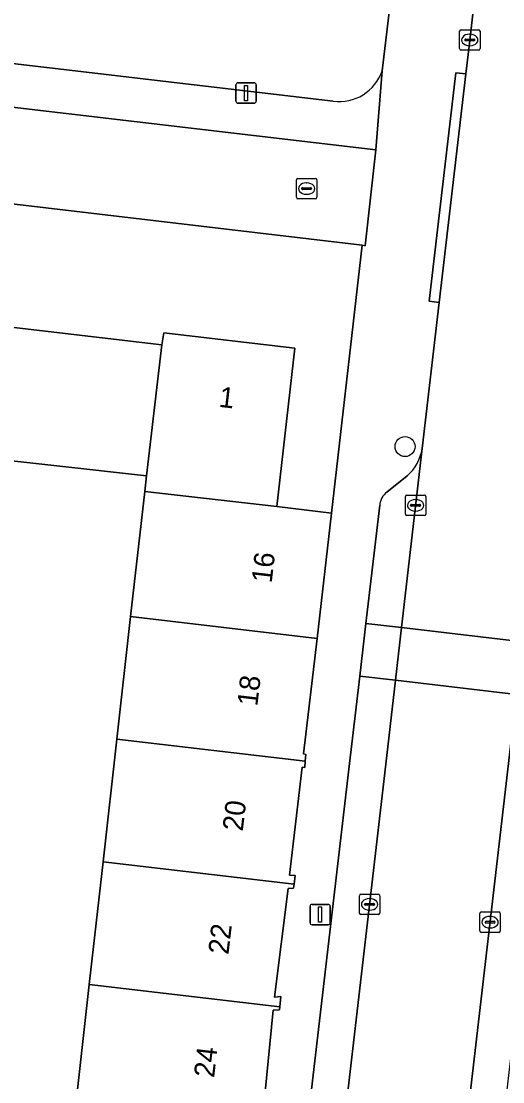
# Model space of a CAD drawing. Extents: x 161241 to 161758, y 384138 to 384885.
# Drawn here: x 161433.6 to 161457.1, y 384527.4 to 384579.4 of the extents above; entities that cross this region are included whole.
import ezdxf

# ---------------------------------------------------------------- set-up
doc = ezdxf.new("R2010")
doc.units = 0
for name, color, linetype in [('IMGEO_Boom', 7, 'Continuous'), ('IMGEO_Erf', 7, 'Continuous'), ('IMGEO_Kolk', 7, 'Continuous'), ('IMGEO_Lichtmast', 7, 'Continuous'), ('IMGEO_Pand', 7, 'Continuous'), ('IMGEO_Pand_nummerreeks', 7, 'Continuous'), ('IMGEO_Parkeervlak_open', 7, 'Continuous'), ('IMGEO_Rijbaan_lokaal_open', 7, 'Continuous'), ('IMGEO_Voetpad_open', 7, 'Continuous')]:
    doc.layers.add(name, color=color, linetype=linetype)

msp = doc.modelspace()

# ---------------------------------------------------------------- linework, layer by layer
at = {"layer": 'IMGEO_Boom'}
msp.add_circle((161452.348, 384558.545), 0.489, dxfattribs=at)
at = {"layer": 'IMGEO_Erf'}
for points in [[(161451.231, 384576.957), (161452.444, 384587.078)], [(161393.526, 384581.977), (161448.824, 384575.465)], [(161431.664, 384564.552), (161440.436, 384563.525), (161440.534, 384564.111), (161446.954, 384563.36), (161446.076, 384555.602), (161448.755, 384555.29), (161450.255, 384568.412), (161432.118, 384570.547)], [(161436.213, 384526.177), (161436.887, 384532.189), (161437.562, 384538.199), (161438.237, 384544.211), (161438.911, 384550.221), (161439.599, 384556.349), (161439.684, 384557.106), (161430.889, 384558.093)]]:
    msp.add_lwpolyline(points, dxfattribs=at)
msp.add_arc((161449.133, 384577.654), 2.21, 261.9554, 341.6307, dxfattribs=at)
at = {"layer": 'IMGEO_Kolk'}
for p, q in [((161455.094, 384578.962), (161455.946, 384578.962)), ((161455.019, 384578.036), (161455.019, 384578.888)), ((161455.278, 384578.456), (161455.278, 384578.468)), ((161455.716, 384578.419), (161455.318, 384578.419)), ((161455.321, 384578.505), (161455.719, 384578.505)), ((161455.507, 384578.742), (161455.532, 384578.742)), ((161455.762, 384578.468), (161455.762, 384578.456)), ((161456.02, 384578.888), (161456.02, 384578.036)), ((161455.946, 384577.962), (161455.094, 384577.962)), ((161455.53, 384578.182), (161455.505, 384578.182)), ((161447.103, 384571.68), (161447.955, 384571.68)), ((161447.028, 384570.754), (161447.028, 384571.606)), ((161447.287, 384571.174), (161447.287, 384571.186)), ((161447.725, 384571.137), (161447.327, 384571.137)), ((161447.33, 384571.223), (161447.728, 384571.223)), ((161447.516, 384571.46), (161447.541, 384571.46)), ((161447.771, 384571.186), (161447.771, 384571.174)), ((161448.029, 384571.606), (161448.029, 384570.754)), ((161447.955, 384570.68), (161447.103, 384570.68)), ((161447.539, 384570.9), (161447.514, 384570.9)), ((161452.365, 384555.24), (161452.365, 384556.092)), ((161452.44, 384556.166), (161453.292, 384556.166)), ((161453.366, 384556.092), (161453.366, 384555.24)), ((161452.624, 384555.66), (161452.624, 384555.672)), ((161453.062, 384555.623), (161452.664, 384555.623)), ((161452.667, 384555.709), (161453.065, 384555.709)), ((161452.853, 384555.946), (161452.878, 384555.946)), ((161453.108, 384555.672), (161453.108, 384555.66)), ((161453.292, 384555.166), (161452.44, 384555.166)), ((161452.876, 384555.386), (161452.851, 384555.386)), ((161450.111, 384535.694), (161450.111, 384536.546)), ((161450.186, 384536.62), (161451.038, 384536.62)), ((161450.599, 384536.4), (161450.624, 384536.4)), ((161451.112, 384536.546), (161451.112, 384535.694)), ((161450.37, 384536.114), (161450.37, 384536.126)), ((161450.808, 384536.077), (161450.41, 384536.077)), ((161450.413, 384536.163), (161450.811, 384536.163)), ((161450.622, 384535.84), (161450.597, 384535.84)), ((161450.854, 384536.126), (161450.854, 384536.114)), ((161451.038, 384535.62), (161450.186, 384535.62)), ((161456.013, 384534.822), (161456.013, 384535.674)), ((161456.088, 384535.748), (161456.94, 384535.748)), ((161456.315, 384535.291), (161456.713, 384535.291)), ((161456.501, 384535.528), (161456.526, 384535.528)), ((161457.014, 384535.674), (161457.014, 384534.822)), ((161456.94, 384534.748), (161456.088, 384534.748)), ((161456.272, 384535.242), (161456.272, 384535.254)), ((161456.71, 384535.205), (161456.312, 384535.205)), ((161456.524, 384534.968), (161456.499, 384534.968)), ((161456.756, 384535.254), (161456.756, 384535.242))]:
    msp.add_line(p, q, dxfattribs=at)
for points in [[(161455.094, 384578.962), (161455.946, 384578.962)], [(161455.019, 384578.036), (161455.019, 384578.888)], [(161456.02, 384578.888), (161456.02, 384578.036)], [(161455.946, 384577.962), (161455.094, 384577.962)], [(161447.103, 384571.68), (161447.955, 384571.68)], [(161447.028, 384570.754), (161447.028, 384571.606)], [(161448.029, 384571.606), (161448.029, 384570.754)], [(161447.955, 384570.68), (161447.103, 384570.68)], [(161452.365, 384555.24), (161452.365, 384556.092)], [(161452.44, 384556.166), (161453.292, 384556.166)], [(161453.366, 384556.092), (161453.366, 384555.24)], [(161453.292, 384555.166), (161452.44, 384555.166)], [(161450.111, 384535.694), (161450.111, 384536.546)], [(161450.186, 384536.62), (161451.038, 384536.62)], [(161451.112, 384536.546), (161451.112, 384535.694)], [(161451.038, 384535.62), (161450.186, 384535.62)], [(161456.013, 384534.822), (161456.013, 384535.674)], [(161456.088, 384535.748), (161456.94, 384535.748)], [(161457.014, 384535.674), (161457.014, 384534.822)], [(161456.94, 384534.748), (161456.088, 384534.748)]]:
    msp.add_lwpolyline(points, dxfattribs=at)
for centre, radius, start, end in [((161455.096, 384578.886), 0.0765, 91.552, 178.448), ((161455.096, 384578.886), 0.0765, 91.552, 178.448), ((161455.944, 384578.886), 0.0765, 1.552, 88.448), ((161455.944, 384578.886), 0.0765, 1.552, 88.448), ((161455.318, 384578.465), 0.0403, 85.8775, 175.7526), ((161455.315, 384578.455), 0.0366, 178.938, 274.7102), ((161455.719, 384578.462), 0.043, 264.8664, 352.4533), ((161455.723, 384578.467), 0.0386, 1.7309, 96.639), ((161455.096, 384578.038), 0.0765, 181.552, 268.448), ((161455.096, 384578.038), 0.0765, 181.552, 268.448), ((161455.944, 384578.038), 0.0765, 271.552, 358.448), ((161455.944, 384578.038), 0.0765, 271.552, 358.448), ((161447.105, 384571.604), 0.0765, 91.552, 178.448), ((161447.105, 384571.604), 0.0765, 91.552, 178.448), ((161447.953, 384571.604), 0.0765, 1.552, 88.448), ((161447.953, 384571.604), 0.0765, 1.552, 88.448), ((161447.327, 384571.183), 0.0403, 85.8775, 175.7526), ((161447.324, 384571.173), 0.0366, 178.938, 274.7102), ((161447.728, 384571.18), 0.043, 264.8664, 352.4533), ((161447.732, 384571.185), 0.0386, 1.7309, 96.639), ((161447.105, 384570.756), 0.0765, 181.552, 268.448), ((161447.105, 384570.756), 0.0765, 181.552, 268.448), ((161447.953, 384570.756), 0.0765, 271.552, 358.448), ((161447.953, 384570.756), 0.0765, 271.552, 358.448), ((161452.442, 384556.09), 0.0765, 91.552, 178.448), ((161452.442, 384556.09), 0.0765, 91.552, 178.448), ((161453.29, 384556.09), 0.0765, 1.552, 88.448), ((161453.29, 384556.09), 0.0765, 1.552, 88.448), ((161452.664, 384555.669), 0.0403, 85.8775, 175.7526), ((161452.661, 384555.659), 0.0366, 178.938, 274.7102), ((161453.065, 384555.666), 0.043, 264.8664, 352.4533), ((161453.069, 384555.671), 0.0386, 1.7309, 96.639), ((161452.442, 384555.242), 0.0765, 181.552, 268.448), ((161452.442, 384555.242), 0.0765, 181.552, 268.448), ((161453.29, 384555.242), 0.0765, 271.552, 358.448), ((161453.29, 384555.242), 0.0765, 271.552, 358.448), ((161450.188, 384536.544), 0.0765, 91.552, 178.448), ((161450.188, 384536.544), 0.0765, 91.552, 178.448), ((161451.036, 384536.544), 0.0765, 1.552, 88.448), ((161451.036, 384536.544), 0.0765, 1.552, 88.448), ((161450.41, 384536.123), 0.0403, 85.8775, 175.7526), ((161450.407, 384536.113), 0.0366, 178.938, 274.7102), ((161450.811, 384536.12), 0.043, 264.8664, 352.4533), ((161450.815, 384536.125), 0.0386, 1.7309, 96.639), ((161450.188, 384535.696), 0.0765, 181.552, 268.448), ((161450.188, 384535.696), 0.0765, 181.552, 268.448), ((161451.036, 384535.696), 0.0765, 271.552, 358.448), ((161451.036, 384535.696), 0.0765, 271.552, 358.448), ((161456.09, 384535.672), 0.0765, 91.552, 178.448), ((161456.09, 384535.672), 0.0765, 91.552, 178.448), ((161456.312, 384535.251), 0.0403, 85.8775, 175.7526), ((161456.717, 384535.253), 0.0386, 1.7309, 96.639), ((161456.938, 384535.672), 0.0765, 1.552, 88.448), ((161456.938, 384535.672), 0.0765, 1.552, 88.448), ((161456.09, 384534.824), 0.0765, 181.552, 268.448), ((161456.09, 384534.824), 0.0765, 181.552, 268.448), ((161456.309, 384535.241), 0.0366, 178.938, 274.7102), ((161456.713, 384535.248), 0.043, 264.8664, 352.4533), ((161456.938, 384534.824), 0.0765, 271.552, 358.448), ((161456.938, 384534.824), 0.0765, 271.552, 358.448)]:
    msp.add_arc(centre, radius, start, end, dxfattribs=at)
for centre, major_axis, ratio, start_param, end_param in [((161455.506, 384578.462), (-0.387, 0.002), 0.722429, 4.712389, 7.853982), ((161455.531, 384578.462), (-0.39, 0.002), 0.717154, 1.570796, 4.712389), ((161447.515, 384571.18), (-0.387, 0.002), 0.722429, 4.712389, 7.853982), ((161447.54, 384571.18), (-0.39, 0.002), 0.717154, 1.570796, 4.712389), ((161452.852, 384555.666), (-0.387, 0.002), 0.722429, 4.712389, 7.853982), ((161452.877, 384555.666), (-0.39, 0.002), 0.717154, 1.570796, 4.712389), ((161450.598, 384536.12), (-0.387, 0.002), 0.722429, 4.712389, 7.853982), ((161450.623, 384536.12), (-0.39, 0.002), 0.717154, 1.570796, 4.712389), ((161456.5, 384535.248), (-0.387, 0.002), 0.722429, 4.712389, 7.853982), ((161456.525, 384535.248), (-0.39, 0.002), 0.717154, 1.570796, 4.712389)]:
    msp.add_ellipse(centre, major_axis=major_axis, ratio=ratio, start_param=start_param, end_param=end_param, dxfattribs=at)
at = {"layer": 'IMGEO_Lichtmast'}
for p, q in [((161444.169, 384576.363), (161444.959, 384576.363)), ((161444.959, 384576.363), (161444.169, 384576.363)), ((161444.069, 384575.463), (161444.069, 384576.263)), ((161444.069, 384576.263), (161444.069, 384575.463)), ((161445.059, 384576.263), (161445.059, 384575.463)), ((161445.059, 384575.463), (161445.059, 384576.263)), ((161444.959, 384575.363), (161444.169, 384575.363)), ((161444.169, 384575.363), (161444.959, 384575.363)), ((161447.696, 384535.219), (161447.696, 384536.019)), ((161447.696, 384536.019), (161447.696, 384535.219)), ((161447.796, 384536.119), (161448.586, 384536.119)), ((161448.586, 384536.119), (161447.796, 384536.119)), ((161448.686, 384536.019), (161448.686, 384535.219)), ((161448.686, 384535.219), (161448.686, 384536.019)), ((161448.586, 384535.119), (161447.796, 384535.119)), ((161447.796, 384535.119), (161448.586, 384535.119))]:
    msp.add_line(p, q, dxfattribs=at)
for points in [[(161444.489, 384576.238), (161444.639, 384576.238), (161444.639, 384575.488), (161444.489, 384575.488), (161444.489, 384576.238)], [(161448.116, 384535.994), (161448.266, 384535.994), (161448.266, 384535.244), (161448.116, 384535.244), (161448.116, 384535.994)]]:
    msp.add_lwpolyline(points, dxfattribs=at)
for centre, start, end in [((161444.169, 384576.263), 90, 180), ((161444.169, 384576.263), 90, 180), ((161444.959, 384576.263), 0, 90), ((161444.959, 384576.263), 360, 90), ((161444.169, 384575.463), 180, 270), ((161444.169, 384575.463), 180, 270), ((161444.959, 384575.463), 270, 0), ((161444.959, 384575.463), 270, 0), ((161447.796, 384536.019), 90, 180), ((161447.796, 384536.019), 90, 180), ((161448.586, 384536.019), 0, 90), ((161448.586, 384536.019), 360, 90), ((161447.796, 384535.219), 180, 270), ((161447.796, 384535.219), 180, 270), ((161448.586, 384535.219), 270, 0), ((161448.586, 384535.219), 270, 0)]:
    msp.add_arc(centre, 0.1, start, end, dxfattribs=at)
at = {"layer": 'IMGEO_Pand'}
for points in [[(161424.542, 384557.899), (161430.788, 384557.198), (161430.889, 384558.093), (161439.684, 384557.106), (161440.436, 384563.525), (161431.664, 384564.552), (161431.905, 384566.233), (161426.007, 384566.969), (161426.028, 384567.075), (161425.621, 384567.124)], [(161439.684, 384557.106), (161439.599, 384556.349), (161446.076, 384555.602), (161446.954, 384563.36), (161440.534, 384564.111), (161440.436, 384563.525)], [(161448.755, 384555.29), (161446.076, 384555.602), (161439.599, 384556.349), (161438.911, 384550.221), (161448.04, 384549.151)], [(161447.484, 384543.465), (161447.381, 384543.492), (161448.04, 384549.151), (161438.911, 384550.221), (161438.237, 384544.211), (161447.459, 384543.13)], [(161446.969, 384537.535), (161446.688, 384537.543), (161447.308, 384542.844), (161447.437, 384542.828), (161447.459, 384543.13), (161438.237, 384544.211), (161437.562, 384538.199), (161446.916, 384537.102)], [(161446.261, 384531.602), (161445.956, 384531.575), (161446.624, 384536.898), (161446.892, 384536.909), (161446.916, 384537.102), (161437.562, 384538.199), (161436.887, 384532.189), (161446.21, 384531.096)], [(161445.896, 384530.942), (161446.196, 384530.954), (161446.21, 384531.096), (161436.887, 384532.189), (161436.213, 384526.177), (161445.323, 384525.109)]]:
    msp.add_lwpolyline(points, close=True, dxfattribs=at)
at = {"layer": 'IMGEO_Parkeervlak_open'}
for points in [[(161451.107, 384555.678), (161450.43, 384549.88), (161452.178, 384549.677), (161453.187, 384558.455)], [(161452.45, 384557.117), (161451.46, 384556.317)], [(161447.539, 384509.648), (161451.359, 384542.556), (161451.881, 384547.095), (161450.128, 384547.299), (161449.597, 384542.748), (161446.111, 384512.773)], [(161455.567, 384511.666), (161459.568, 384546.2), (161457.814, 384546.404), (161453.447, 384508.842)]]:
    msp.add_lwpolyline(points, dxfattribs=at)
msp.add_lwpolyline([(161450.128, 384547.299), (161451.881, 384547.095), (161452.178, 384549.677), (161450.43, 384549.88)], close=True, dxfattribs=at)
for centre, radius, start, end in [((161451.05, 384558.76), 2.159, 310.4335, 351.8726), ((161452.069, 384555.564), 0.969, 128.9499, 173.2154)]:
    msp.add_arc(centre, radius, start, end, dxfattribs=at)
at = {"layer": 'IMGEO_Rijbaan_lokaal_open'}
for points in [[(161458.88, 384607.496), (161456.155, 384584.108), (161455.501, 384578.293), (161455.326, 384576.798), (161454.02, 384565.608), (161453.187, 384558.455), (161452.178, 384549.677), (161458.115, 384548.986), (161459.149, 384557.883), (161459.972, 384564.87), (161461.287, 384576.027), (161461.494, 384577.785), (161462.171, 384583.365), (161464.9, 384606.794)], [(161452.178, 384549.677), (161451.881, 384547.095), (161457.814, 384546.404), (161458.115, 384548.986)]]:
    msp.add_lwpolyline(points, close=True, dxfattribs=at)
for points in [[(161358.492, 384579.061), (161360.348, 384578.831), (161378.37, 384576.849), (161415.137, 384572.53), (161414.97, 384570.779), (161418.982, 384570.31), (161419.169, 384572.05), (161432.118, 384570.547), (161450.255, 384568.412), (161450.399, 384568.382), (161450.927, 384573.072), (161397.745, 384579.321)], [(161452.684, 384502.539), (161453.058, 384505.828), (161453.447, 384508.842), (161457.814, 384546.404), (161451.881, 384547.095), (161451.359, 384542.556), (161447.539, 384509.648), (161446.771, 384503.468)]]:
    msp.add_lwpolyline(points, dxfattribs=at)
at = {"layer": 'IMGEO_Voetpad_open'}
for points in [[(161452.444, 384587.078), (161451.231, 384576.957), (161450.927, 384573.072), (161450.399, 384568.382), (161450.255, 384568.412), (161448.755, 384555.29), (161448.04, 384549.151), (161447.381, 384543.492), (161447.484, 384543.465), (161447.459, 384543.13), (161447.437, 384542.828), (161447.308, 384542.844), (161446.688, 384537.543), (161446.969, 384537.535), (161446.916, 384537.102), (161446.892, 384536.909), (161446.624, 384536.898), (161445.956, 384531.575), (161446.261, 384531.602), (161446.21, 384531.096), (161446.196, 384530.954), (161445.896, 384530.942), (161445.323, 384525.109)], [(161453.187, 384558.455), (161454.02, 384565.608), (161453.524, 384565.665), (161454.83, 384576.855), (161455.326, 384576.798), (161455.501, 384578.293), (161456.155, 384584.108)], [(161448.824, 384575.465), (161393.526, 384581.977)], [(161397.745, 384579.321), (161450.927, 384573.072), (161451.231, 384576.957)], [(161451.46, 384556.317), (161452.45, 384557.117)], [(161446.111, 384512.773), (161449.597, 384542.748), (161450.128, 384547.299), (161450.43, 384549.88), (161451.107, 384555.678)]]:
    msp.add_lwpolyline(points, dxfattribs=at)
msp.add_lwpolyline([(161454.02, 384565.608), (161455.326, 384576.798), (161454.83, 384576.855), (161453.524, 384565.665)], close=True, dxfattribs=at)
for centre, radius, start, end in [((161449.133, 384577.654), 2.21, 261.9554, 341.6307), ((161451.05, 384558.76), 2.159, 310.4335, 351.8726), ((161452.069, 384555.564), 0.969, 128.9499, 173.2154)]:
    msp.add_arc(centre, radius, start, end, dxfattribs=at)

# ---------------------------------------------------------------- texts
at = {"layer": 'IMGEO_Pand_nummerreeks'}
for s, rotation, p in [('1', 353.328, (161443.202, 384560.496)), ('16', 83.3656, (161445.816, 384551.833)), ('18', 83.3656, (161445.114, 384545.801)), ('20', 83.3656, (161444.401, 384539.674)), ('22', 83.3656, (161443.699, 384533.633)), ('24', 83.3656, (161442.997, 384527.601))]:
    msp.add_text(s, height=1, rotation=rotation, dxfattribs=at).set_placement(p)

doc.saveas('drawing.dxf')
